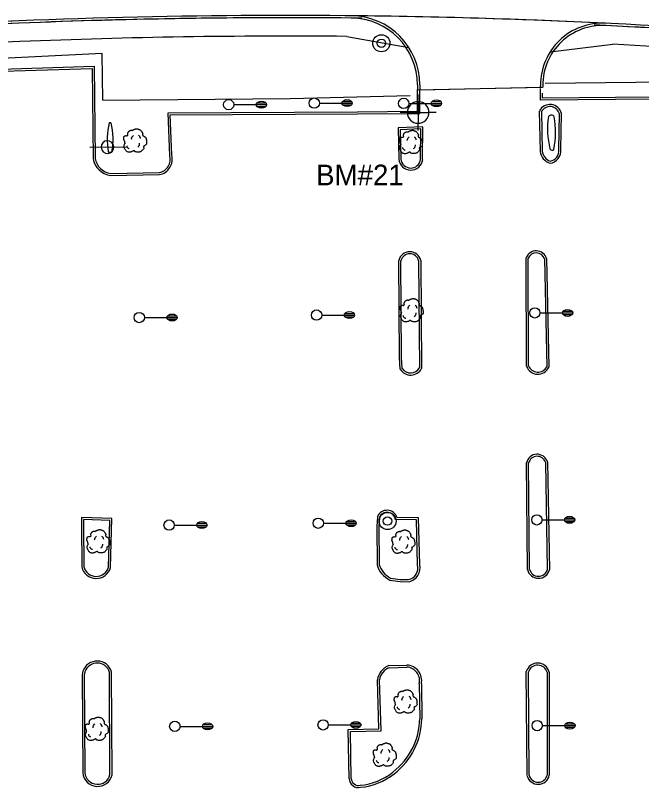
# Model space of a CAD drawing. Extents: x 2145380 to 2157287, y 139568 to 149130.
# Drawn here: x 2148110.3 to 2148291.9, y 142715.8 to 142939.8 of the extents above; entities that cross this region are included whole.
import ezdxf

# ---------------------------------------------------------------- set-up
doc = ezdxf.new("R2010")
doc.units = 0
for name, color, linetype in [('Default', 7, 'Continuous'), ('PR_PREVIOUSLY CONSTRUCTED', 7, 'Continuous'), ('SURV_Benchmark', 7, 'Continuous'), ('TOPO_Concrete', 7, 'Continuous'), ('TOPO_Curb Back', 7, 'Continuous'), ('TOPO_Guardrail', 7, 'Continuous'), ('TOPO_Light Pole', 7, 'Continuous'), ('TOPO_San Manhole', 7, 'Continuous'), ('TOPO_Sign', 7, 'Continuous'), ('TOPO_Tree', 7, 'Continuous')]:
    doc.layers.add(name, color=color, linetype=linetype)

# ---------------------------------------------------------------- blocks, each defined once
blk = doc.blocks.new('LP')
at = {"layer": 'TOPO_Light Pole'}
blk.add_line((3.81, 0), (20.32, 0), dxfattribs=at)
for points in [[(20.32, 0), (27.94, 0)], [(20.32, 0), (23.5, 0)], [(20.83, 1.27), (27.43, 1.27)], [(20.83, 1.27), (23.5, 1.27)], [(23.71, 1.27), (27.43, 1.27)], [(23.71, 0), (27.94, 0)], [(20.83, -1.27), (27.43, -1.27)], [(20.83, -1.27), (23.5, -1.27)], [(23.71, -1.27), (27.43, -1.27)]]:
    blk.add_lwpolyline(points, dxfattribs=at)
blk.add_circle((0, 0), 3.81, dxfattribs=at)
blk.add_ellipse((24.13, 0), major_axis=(3.81, 0), ratio=0.666667, dxfattribs=at)
blk = doc.blocks.new('TREE')
at = {"layer": 'TOPO_Tree'}
for points in [[(-14.1, -0.4), (-14.2, 0.5), (-14.4, 1.4), (-14.6, 2.3), (-14.8, 3.2), (-15.5, 4), (-15.7, 4.9), (-15.8, 5.6), (-15.7, 6.3), (-15.7, 7), (-15.6, 7.9), (-15.7, 8.8), (-15.1, 9.7), (-14.6, 10.4), (-13.8, 10.5), (-13, 10.7), (-12.2, 11), (-11.1, 10), (-10.4, 10.7), (-9.4, 11.7), (-10.3, 13.3), (-9.8, 14.4), (-9.6, 15.1), (-9.3, 15.9), (-8.8, 16.5), (-8.2, 17.3), (-7.5, 17.7), (-6.7, 18.1), (-6.1, 18.4), (-5.6, 18.6), (-5.1, 18.7), (-4.5, 18.7), (-4, 18.5), (-3.5, 18.1)], [(-3.5, 17.6), (-3.1, 18.3), (-2.6, 18.8), (-1.9, 19.2), (-1, 19.7), (-0.2, 20), (0.7, 20.2), (1.6, 20.5), (2.5, 20.8), (3.4, 20.8), (4.1, 20.7), (4.8, 20.5), (5.5, 20.2), (6.4, 19.9), (7.3, 19.7), (8.2, 19.2), (9.4, 18.4), (10, 17.2), (10.8, 16), (11.2, 15.3), (11.6, 14.6), (11.9, 13.9), (12.2, 13.1), (11.4, 12), (11.9, 11.2), (12, 11), (12.2, 10.9), (12.4, 10.7), (12.9, 10.4), (13.5, 10), (14, 9.7), (14.7, 9.2), (15.4, 8.7), (16.1, 8.1), (16.7, 7.5), (16.9, 6.7), (17.1, 6), (17.6, 4.4), (17.7, 2.8), (17.7, 1.2), (17.7, -0.2), (17.8, -2.2), (16.6, -3), (15.5, -3.8), (14.3, -4.6), (13.2, -5.3)], [(13.2, -5.3), (13.3, -5.8), (13.4, -6.3), (13.4, -6.7), (13.8, -8.5), (12.2, -10), (10.8, -11.5), (10, -12.3), (9.1, -12.8), (8.2, -13.1), (6, -13.8), (3.3, -13.6), (1.3, -13.1), (0.5, -12.9), (-0.1, -11.4), (-0.8, -11.5), (-2, -11.6), (-3.3, -12.8), (-4.5, -13.1), (-6.1, -13.5), (-7.8, -14), (-9.3, -13.6), (-11.4, -13.1), (-12.8, -11.4), (-14.1, -9.4), (-15.3, -7.3), (-15.6, -5.1), (-15.1, -3), (-14.9, -1.9), (-13.9, -0.8), (-13.5, 0.1)], [(-4.2, 5.1), (-4.5, 6.1), (-4.3, 7.2), (-3.8, 8.2), (-3.3, 9.3), (-2.7, 10.3), (-1.6, 11)], [(5.9, 11.2), (6.5, 10.7), (7, 10.2), (7.4, 9.5), (7.9, 8.6), (8.3, 7.6), (8.5, 6.6)], [(-11.4, -4.5), (-11.5, -5.4), (-11, -6.3), (-10.1, -7.2), (-9.3, -8), (-8.5, -8.3), (-7.7, -8.1)], [(4.8, -6.3), (5.7, -5.7), (6.3, -4.9), (6.8, -3.9), (7.4, -2.8), (7.6, -1.7), (7.5, -0.6)]]:
    blk.add_open_spline(points, degree=3, dxfattribs=at)
blk = doc.blocks.new('EXMHSS')
at = {"layer": 'Default'}
for radius in [6.3, 3.13]:
    blk.add_circle((0, 0), radius, dxfattribs=at)
blk = doc.blocks.new('BM')
at = {"layer": 'SURV_Benchmark'}
for p, q in [((0, 2.49), (0, 4.15)), ((-2.49, 0), (-4.16, 0)), ((4.16, 0), (2.49, 0)), ((0, -4.16), (0, -2.49))]:
    blk.add_line(p, q, dxfattribs=at)
for points in [[(0, 2.49), (0, 2.49), (0, 0), (2.49, 0), (2.49, 0), (2.49, 0)], [(0, 2.49), (0, 2.49), (0, 0), (2.49, 0), (2.49, 0), (2.49, 0), (2.49, 0)], [(-2.5, 0), (-2.49, 0), (0, 0), (0, -2.49), (0, -2.49)], [(-2.5, 0), (-2.49, 0), (0, 0), (0, -2.49), (0, -2.49)]]:
    blk.add_lwpolyline(points, dxfattribs=at)
for start, end in [(90.0638, 180.0068), (0.0638, 90.0068), (0.0638, 90.0068), (180.0638, 270.0068), (180.0638, 270.0068), (269.9472, 359.9927)]:
    blk.add_arc((0, 0), 2.5, start, end, dxfattribs=at)

msp = doc.modelspace()

# ---------------------------------------------------------------- linework, layer by layer
at = {"layer": 'PR_PREVIOUSLY CONSTRUCTED'}
for p, q in [((2148111.41, 142938.19), (2147495.09, 142912.98)), ((2148111.44, 142937.52), (2148061.26, 142935.47)), ((2148111.66, 142932.19), (2148063.05, 142930.21)), ((2148206.44, 142933.69), (2148224.44, 142930.44)), ((2148265.4, 142929.22), (2148283.56, 142931.4)), ((2148226.91, 142919.64), (2148226.91, 142918.15)), ((2148226.91, 142918.15), (2148263.24, 142919.01)), ((2148227.58, 142919.64), (2148227.57, 142918.17)), ((2148262.57, 142919.46), (2148262.57, 142918.99)), ((2148263.24, 142919.46), (2148263.24, 142919.01))]:
    msp.add_line(p, q, dxfattribs=at)
for centre, radius, start, end in [((2148188.94, 141042.91), 1896.86, 84.04429, 92.3423), ((2148188.94, 141042.91), 1896.19, 89.43093, 92.3423), ((2148207.58, 142919.68), 20, 359.881, 89.4309), ((2148207.58, 142919.68), 19.33, 359.881, 89.4309), ((2148280.57, 142919.54), 18, 87.2045, 180.2468), ((2148280.57, 142919.54), 17.33, 87.2045, 180.2468), ((2148188.94, 141042.91), 1896.19, 84.04429, 87.20446), ((2148188.94, 141042.91), 1890.86, 89.46962, 92.3423), ((2148188.94, 141042.91), 1890.86, 84.04429, 87.13158)]:
    msp.add_arc(centre, radius, start, end, dxfattribs=at)
at = {"layer": 'TOPO_Concrete'}
msp.add_lwpolyline([(2148227.58, 142919.64), (2148227.57, 142918.17), (2148262.57, 142918.99), (2148262.57, 142919.46)], dxfattribs=at)
for centre, radius, start, end in [((2148188.94, 141042.91), 1896.86, 87.20455, 89.43086), ((2148207.58, 142919.68), 20, 359.881, 89.4244), ((2148280.57, 142919.54), 18, 87.2144, 180.2468)]:
    msp.add_arc(centre, radius, start, end, dxfattribs=at)
at = {"layer": 'TOPO_Curb Back'}
for p, q in [((2148228.5, 142907.48), (2148221.33, 142907.18)), ((2148221.33, 142907.18), (2148221.52, 142898.08)), ((2148228.42, 142897.96), (2148228.5, 142907.48)), ((2148227.9, 142906.86), (2148221.94, 142906.61)), ((2148221.94, 142906.61), (2148222.12, 142898.11)), ((2148227.82, 142898), (2148227.9, 142906.86)), ((2148221.7, 142840.5), (2148221.51, 142868.68)), ((2148222.3, 142840.52), (2148222.11, 142868.62)), ((2148227.26, 142868.62), (2148227.49, 142837.52)), ((2148227.86, 142868.69), (2148228.09, 142837.37)), ((2148221.93, 142837.18), (2148221.7, 142840.5)), ((2148222.52, 142837.37), (2148222.3, 142840.52)), ((2148138.29, 142793.84), (2148129.51, 142794.13)), ((2148129.51, 142794.13), (2148129.52, 142792.06)), ((2148137.68, 142793.26), (2148130.11, 142793.51)), ((2148130.11, 142793.51), (2148130.12, 142792.07)), ((2148137.34, 142779.71), (2148137.68, 142793.26)), ((2148137.93, 142779.62), (2148138.29, 142793.84)), ((2148215.28, 142794.34), (2148215.15, 142791.46)), ((2148215.88, 142794.2), (2148215.75, 142791.45)), ((2148226.66, 142793.46), (2148220.53, 142793.49)), ((2148227.25, 142794.06), (2148221.01, 142794.09)), ((2148226.96, 142780.37), (2148226.66, 142793.46)), ((2148227.56, 142780.45), (2148227.25, 142794.06)), ((2148129.52, 142792.06), (2148129.55, 142779.77)), ((2148130.12, 142792.07), (2148130.15, 142779.84)), ((2148215.15, 142791.46), (2148215.19, 142780.42)), ((2148215.75, 142791.45), (2148215.79, 142780.51)), ((2148221.89, 142775.51), (2148224.41, 142775.5)), ((2148221.94, 142776.11), (2148224.35, 142776.1)), ((2148218.65, 142751.14), (2148223.84, 142751.31)), ((2148218.76, 142750.55), (2148223.84, 142750.71)), ((2148129.89, 142749.49), (2148129.72, 142748.43)), ((2148129.72, 142748.43), (2148129.89, 142720)), ((2148130.47, 142749.35), (2148130.32, 142748.38)), ((2148130.32, 142748.38), (2148130.49, 142720.03)), ((2148137.75, 142719.54), (2148137.64, 142749.19)), ((2148138.35, 142719.47), (2148138.24, 142749.27)), ((2148215.73, 142732.78), (2148215.32, 142747.03)), ((2148216.34, 142732.19), (2148215.92, 142747)), ((2148227.44, 142745.89), (2148227.57, 142735.74)), ((2148228.04, 142745.83), (2148228.17, 142735.74)), ((2148206.84, 142732.62), (2148215.73, 142732.78)), ((2148207.12, 142718.41), (2148206.84, 142732.62)), ((2148207.45, 142732.03), (2148216.34, 142732.19)), ((2148207.72, 142718.43), (2148207.45, 142732.03))]:
    msp.add_line(p, q, dxfattribs=at)
for points in [[(2148111.41, 142938.19), (2147495.09, 142912.98)], [(2148111.44, 142937.52), (2147875.92, 142927.89)], [(2148058.56, 142897.97), (2148057.62, 142922.43), (2148100.06, 142923.97), (2148133.15, 142925.02), (2148133.45, 142898.29)], [(2148059.16, 142897.99), (2148058.24, 142921.86), (2148100.08, 142923.37), (2148132.56, 142924.4), (2148132.86, 142898.23)], [(2148457.7, 142903.8), (2148457.32, 142916.65), (2148402.67, 142916.37), (2148375.98, 142915.72), (2148284.31, 142915.37), (2148262.59, 142915.18), (2148262.58, 142918.56)], [(2148155.08, 142899.11), (2148154.59, 142911.52), (2148209.52, 142911.84), (2148226.96, 142911.97), (2148226.97, 142918.25)], [(2148155.67, 142899.2), (2148155.22, 142910.92), (2148209.53, 142911.24), (2148227.56, 142911.37), (2148227.57, 142918.27)], [(2148458.3, 142903.8), (2148457.9, 142917.25), (2148402.66, 142916.97), (2148375.97, 142916.32), (2148284.3, 142915.97), (2148263.19, 142915.78), (2148263.18, 142917.19)], [(2148262.24, 142911.99), (2148262.47, 142900.36)], [(2148262.84, 142912), (2148263.07, 142900.4)], [(2148267.86, 142900.87), (2148268.07, 142911.23)], [(2148268.46, 142900.9), (2148268.67, 142911.31)], [(2148137.97, 142893.95), (2148152.07, 142894.19)], [(2148137.94, 142893.35), (2148152.13, 142893.59)], [(2148258.55, 142838.07), (2148258.43, 142869.42)], [(2148259.15, 142838.07), (2148259.03, 142869.31)], [(2148263.74, 142869.16), (2148264.39, 142837.83)], [(2148264.34, 142869.26), (2148264.99, 142837.7)], [(2148258.81, 142779.07), (2148258.55, 142810)], [(2148259.41, 142779.08), (2148259.15, 142809.93)], [(2148264.05, 142810.14), (2148264.56, 142779.02)], [(2148264.65, 142810.24), (2148265.16, 142778.95)], [(2148258.69, 142719.28), (2148258.47, 142749.45)], [(2148259.29, 142719.29), (2148259.07, 142749.36)], [(2148264.5, 142749.21), (2148264.53, 142719.39)], [(2148265.1, 142749.29), (2148265.13, 142719.33)]]:
    msp.add_lwpolyline(points, dxfattribs=at)
for centre, radius, start, end in [((2148188.94, 141042.91), 1896.86, 84.04429, 92.3423), ((2148188.94, 141042.91), 1896.19, 89.34054, 92.3423), ((2148188.94, 141042.91), 1896.19, 84.04429, 87.30356), ((2148265.31, 142910.48), 3.45, 13.7322, 151.4824), ((2148265.31, 142910.48), 2.85, 15.2323, 151.4824), ((2148264.92, 142900.45), 3.57, 276.759, 7.157), ((2148264.92, 142900.45), 2.97, 279.2375, 7.9613), ((2148138.64, 142899.17), 5.86, 189.1581, 263.1315), ((2148138.64, 142899.17), 5.26, 189.6319, 262.6955), ((2148151.29, 142898.04), 3.93, 281.3243, 15.7487), ((2148151.29, 142898.04), 4.53, 280.6121, 14.817), ((2148266.58, 142900.87), 4.15, 187.1431, 252.5655), ((2148266.58, 142900.87), 3.55, 187.6333, 250.4642), ((2148224.98, 142898.37), 3.47, 184.8868, 353.1655), ((2148224.98, 142898.37), 2.87, 185.2526, 352.5331), ((2148261.36, 142868.36), 3.11, 16.7832, 159.9916), ((2148224.68, 142867.96), 3.26, 12.9205, 167.1848), ((2148224.68, 142867.96), 2.66, 14.2658, 165.7612), ((2148261.36, 142868.36), 2.51, 18.5583, 157.6788), ((2148261.83, 142839.15), 3.48, 200.0239, 335.2362), ((2148261.83, 142839.15), 2.88, 200.0239, 332.6065), ((2148224.96, 142838.94), 3.5, 210.027, 333.4485), ((2148224.96, 142838.94), 2.9, 212.6577, 330.7328), ((2148261.63, 142809.32), 3.15, 17.0037, 167.6537), ((2148261.63, 142809.32), 2.55, 18.8047, 166.22), ((2148218.1, 142793.15), 3.06, 17.7919, 157.1707), ((2148218.1, 142793.15), 2.46, 7.8675, 154.8093), ((2148133.76, 142780.76), 4.32, 193.3034, 344.7044), ((2148133.76, 142780.76), 3.72, 194.3282, 343.6238), ((2148222.02, 142782.39), 7.11, 196.1319, 244.2633), ((2148222.02, 142782.39), 6.51, 196.854, 243.5476), ((2148223.59, 142779.49), 3.48, 282.5217, 14.6162), ((2148223.59, 142779.49), 4.08, 281.5424, 13.5913), ((2148262, 142779.74), 3.27, 192.9919, 345.9105), ((2148262, 142779.74), 2.67, 192.9919, 344.2932), ((2148236.51, 142875.86), 101.41, 260.0204, 261.7118), ((2148236.51, 142875.86), 100.81, 260.0686, 261.6878), ((2148134.03, 142748.11), 4.37, 15.4418, 161.5346), ((2148134.03, 142748.11), 3.77, 16.6172, 160.7824), ((2148220.3, 142746.4), 5.02, 109.2526, 172.8377), ((2148220.3, 142746.4), 4.42, 110.4099, 172.2582), ((2148223.6, 142746.77), 4.54, 348.0091, 86.8716), ((2148223.6, 142746.77), 3.94, 347.0702, 86.511), ((2148261.76, 142748.44), 3.44, 14.1829, 163.009), ((2148261.76, 142748.44), 2.84, 15.6117, 161.2423), ((2148207.6, 142736.07), 19.97, 307.6774, 359.0688), ((2148207.6, 142736.07), 20.57, 307.6895, 359.0933), ((2148134.16, 142720.39), 4.29, 185.1428, 347.6946), ((2148134.16, 142720.39), 3.69, 185.5194, 346.7109), ((2148208.61, 142734.34), 17.99, 275.4677, 308.5085), ((2148208.61, 142734.34), 18.59, 275.5971, 308.495), ((2148261.9, 142720), 3.29, 193.7117, 348.2514), ((2148261.9, 142720), 2.69, 193.7117, 346.9977), ((2148209.82, 142718.47), 2.7, 181.139, 282.9405), ((2148209.82, 142718.47), 2.1, 181.139, 283.9352)]:
    msp.add_arc(centre, radius, start, end, dxfattribs=at)
at = {"layer": 'TOPO_Guardrail'}
for points in [[(2148135.71, 142915.24), (2148135.52, 142928.73), (2148055.75, 142924.73), (2148057.61, 142896.71)], [(2148456.68, 142921.19), (2148398.22, 142921.07), (2148307.75, 142920.52), (2148263.98, 142920.05)], [(2148135.71, 142915.24), (2148190.04, 142915.69), (2148224.81, 142916.53)]]:
    msp.add_lwpolyline(points, dxfattribs=at)
at = {"layer": 'TOPO_Sign'}
msp.add_line((2148266.56, 142910.39), (2148266.56, 142910.39), dxfattribs=at)
for points in [[(2148138.05, 142908.58), (2148138.05, 142908.58), (2148137.52, 142908.63)], [(2148131.9, 142901.57), (2148142.78, 142901.63)], [(2148137.27, 142900.19), (2148138.32, 142900.09), (2148138.32, 142900.09)]]:
    msp.add_lwpolyline(points, dxfattribs=at)
for centre, radius, start, end in [((2148287.91, 142906.78), 23.3, 171.004, 194.2442), ((2148265.72, 142909.93), 0.957, 28.5494, 149.4512), ((2148242.04, 142905.86), 24.93, 348.5856, 10.4687), ((2148157.04, 142903.82), 20.1, 166.1576, 190.4271), ((2148118.65, 142903.71), 20.01, 349.5558, 14.0793), ((2148137.04, 142901.59), 1.84, 47.4196, 227.4196), ((2148137.04, 142901.59), 1.84, 227.4196, 47.4196), ((2148265.94, 142901.32), 0.671, 204.235, 324.1699)]:
    msp.add_arc(centre, radius, start, end, dxfattribs=at)

# ---------------------------------------------------------------- block references
at = {"layer": 'SURV_Benchmark', "xscale": 1.25, "yscale": 1.25}
msp.add_blockref('BM', (2148227.11, 142911.61), dxfattribs=at)
at = {"layer": 'TOPO_Light Pole', "xscale": 0.39370000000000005, "yscale": 0.3937000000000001}
for p in [(2148172.17, 142913.89), (2148196.99, 142914.33), (2148222.91, 142914.27), (2148146.25, 142852.14), (2148197.67, 142852.84), (2148260.94, 142853.48), (2148154.9, 142791.93), (2148198.15, 142792.47), (2148261.53, 142793.44), (2148156.56, 142733.53), (2148199.56, 142733.95), (2148261.63, 142733.75)]:
    msp.add_blockref('LP', p, dxfattribs=at)
at = {"layer": 'TOPO_San Manhole', "xscale": 0.39370000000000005, "yscale": 0.3937000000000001}
for p in [(2148216.44, 142931.7), (2148218.24, 142793.1)]:
    msp.add_blockref('EXMHSS', p, dxfattribs=at)
at = {"layer": 'TOPO_Tree', "xscale": 0.19685000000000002, "yscale": 0.19685000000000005}
for p in [(2148144.88, 142902.8), (2148224.83, 142902.37), (2148225.04, 142853.57), (2148134.18, 142786.52), (2148222.62, 142786.43), (2148223.29, 142740.06), (2148133.74, 142732.13), (2148217.23, 142724.62)]:
    msp.add_blockref('TREE', p, dxfattribs=at)

# ---------------------------------------------------------------- texts
at = {"layer": 'SURV_Benchmark'}
msp.add_text('BM#21', height=6, dxfattribs=at).set_placement((2148197.52, 142890.49))

doc.saveas('drawing.dxf')
